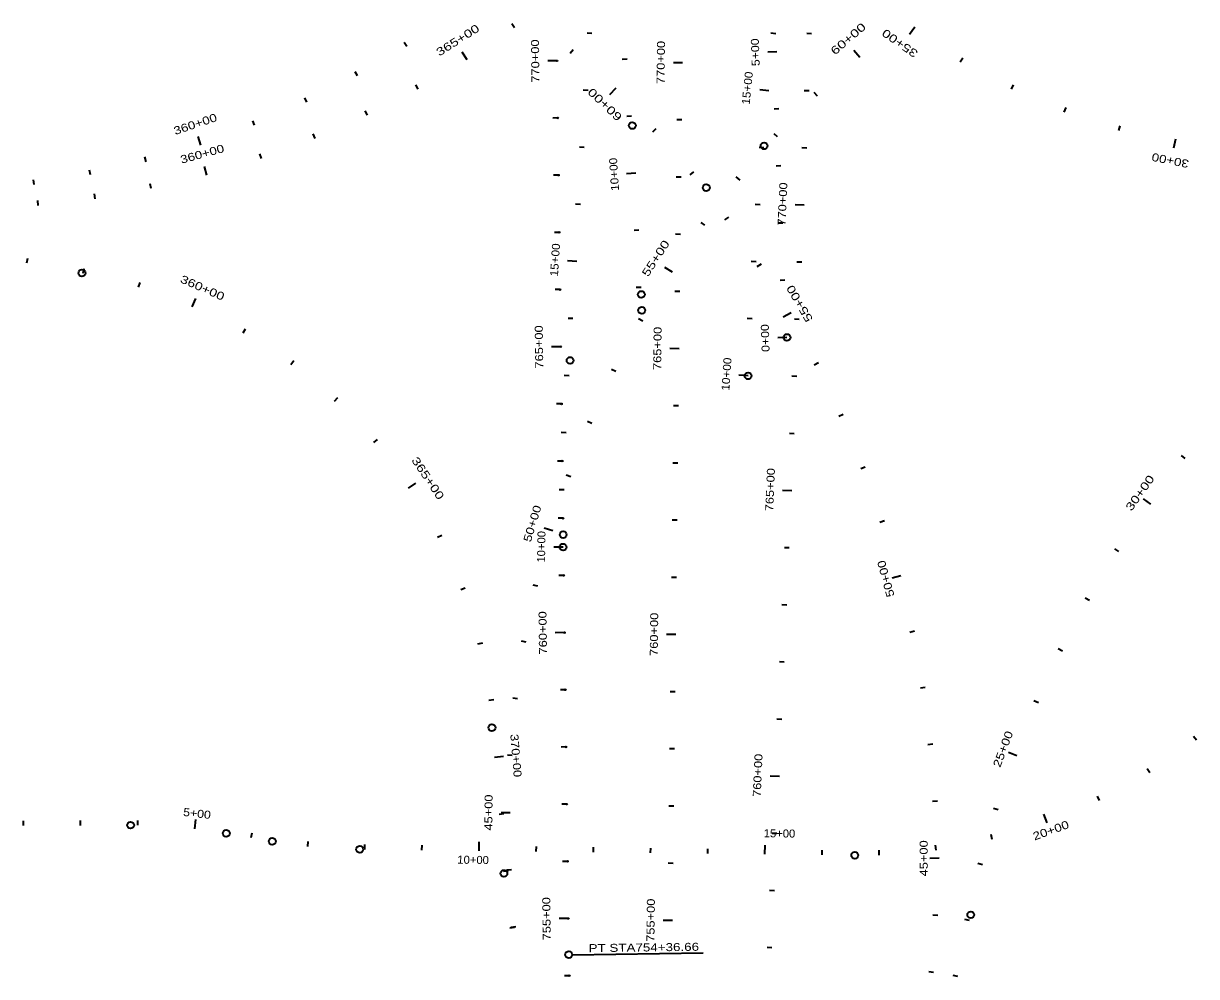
# Model space of a CAD drawing. Extents: x 2357892 to 2370172, y 6966790 to 6985499.
# Drawn here: x 2363338 to 2365390, y 6976228 to 6977895 of the extents above; entities that cross this region are included whole.
import ezdxf
from ezdxf.enums import TextEntityAlignment as Align

# ---------------------------------------------------------------- set-up
doc = ezdxf.new("R2010")
doc.units = 0
doc.header["$LTSCALE"] = 5.6
doc.header["$PDMODE"] = 32
doc.header["$PDSIZE"] = 2.8
doc.layers.add('28', color=7, linetype='Continuous', lineweight=35)
doc.layers.add('7', color=7, linetype='Continuous')

msp = doc.modelspace()

# ---------------------------------------------------------------- linework, layer by layer
at = {"layer": '28'}
for p, q in [((2364196.98, 6977887.49), (2364191.996, 6977894.375)), ((2364332.276, 6977877.606), (2364323.794, 6977878.17)), ((2364653.944, 6977876.548), (2364645.525, 6977877.717)), ((2364716.73, 6977876.916), (2364708.238, 6977877.286)), ((2364896.982, 6977888.495), (2364887.77, 6977875.413)), ((2364008.325, 6977854.335), (2364003.75, 6977861.499)), ((2364114.27, 6977831.311), (2364105.68, 6977844.81)), ((2364299.669, 6977848.715), (2364294.191, 6977842.216)), ((2364393.784, 6977832.501), (2364385.31, 6977831.829)), ((2364656.095, 6977845.54), (2364640.105, 6977844.983)), ((2364800.917, 6977835.329), (2364790.467, 6977847.445)), ((2364981.039, 6977834.378), (2364976.738, 6977827.047)), ((2364271.182, 6977829.601), (2364255.183, 6977829.39)), ((2364490.822, 6977826.107), (2364474.823, 6977826.296)), ((2363922.455, 6977803.116), (2363918.326, 6977810.546)), ((2364028.346, 6977780.183), (2364024.22, 6977787.615)), ((2364325.637, 6977777.826), (2364317.156, 6977778.391)), ((2364374.112, 6977781.967), (2364363.072, 6977770.386)), ((2364641.92, 6977777.279), (2364626.005, 6977778.925)), ((2364712.385, 6977777.011), (2364703.893, 6977777.38)), ((2364727.074, 6977767.895), (2364721.167, 6977774.007)), ((2365069.289, 6977787.407), (2365065.609, 6977779.745)), ((2363833.619, 6977757.236), (2363829.951, 6977764.903)), ((2363939.516, 6977734.289), (2363935.842, 6977741.954)), ((2364272.498, 6977729.609), (2364263.998, 6977729.497)), ((2364401.686, 6977732.813), (2364393.213, 6977732.142)), ((2364659.573, 6977745.6), (2364651.078, 6977745.304)), ((2365161.125, 6977747.905), (2365158.093, 6977739.964)), ((2363742.148, 6977716.864), (2363738.955, 6977724.741)), ((2364444.34, 6977710.8), (2364438.111, 6977705.017)), ((2364489.642, 6977726.114), (2364481.142, 6977726.214)), ((2365255.917, 6977716.144), (2365253.552, 6977707.979)), ((2363648.383, 6977682.151), (2363643.288, 6977697.319)), ((2363848.099, 6977693.793), (2363844.891, 6977701.664)), ((2364657.174, 6977696.383), (2364650.93, 6977702.15)), ((2365353.013, 6977692.341), (2365349.851, 6977676.657)), ((2364318.999, 6977678.047), (2364310.517, 6977678.611)), ((2364633.366, 6977677.65), (2364624.886, 6977678.24)), ((2364708.041, 6977677.105), (2364699.549, 6977677.474)), ((2363552.673, 6977653.228), (2363550.464, 6977661.436)), ((2363754.422, 6977658.841), (2363751.691, 6977666.89)), ((2363455.376, 6977630.201), (2363453.672, 6977638.529)), ((2363658.822, 6977629.557), (2363654.596, 6977644.988)), ((2364273.814, 6977629.618), (2364265.314, 6977629.506)), ((2364408.981, 6977633.081), (2364393.014, 6977632.049)), ((2364510.093, 6977635.477), (2364503.522, 6977630.086)), ((2364591.441, 6977621.023), (2364584.88, 6977626.426)), ((2364663.051, 6977645.661), (2364654.556, 6977645.365)), ((2363356.855, 6977613.158), (2363355.663, 6977621.574)), ((2363561.64, 6977606.046), (2363559.89, 6977614.364)), ((2364488.462, 6977626.121), (2364479.962, 6977626.221)), ((2363463.226, 6977588.394), (2363461.976, 6977596.802)), ((2363363.931, 6977576.663), (2363363.187, 6977585.13)), ((2364312.36, 6977578.268), (2364303.879, 6977578.832)), ((2364626.425, 6977577.891), (2364617.945, 6977578.481)), ((2364703.697, 6977577.2), (2364687.712, 6977577.895)), ((2364530.087, 6977542.057), (2364523.23, 6977547.079)), ((2364571.27, 6977556.39), (2364564.41, 6977551.37)), ((2364666.529, 6977545.721), (2364658.034, 6977545.425)), ((2364275.129, 6977529.627), (2364266.63, 6977529.515)), ((2364414.558, 6977533.238), (2364406.067, 6977532.838)), ((2364487.281, 6977526.128), (2364478.782, 6977526.228)), ((2363344.095, 6977476.375), (2363345.651, 6977484.731)), ((2363442.405, 6977458.069), (2363443.981, 6977466.422)), ((2364305.722, 6977478.488), (2364289.757, 6977479.55)), ((2364473.309, 6977459.739), (2364459.886, 6977468.446)), ((2364619.484, 6977478.133), (2364611.004, 6977478.723)), ((2364628.179, 6977474.176), (2364621.066, 6977469.523)), ((2364699.353, 6977477.294), (2364690.861, 6977477.663)), ((2363539.409, 6977433.996), (2363541.921, 6977442.116)), ((2364670.006, 6977445.782), (2364661.511, 6977445.486)), ((2364276.445, 6977429.635), (2364267.946, 6977429.523)), ((2364418.391, 6977433.313), (2364409.895, 6977433.061)), ((2364486.101, 6977426.135), (2364477.601, 6977426.235)), ((2363633.064, 6977399.096), (2363639.492, 6977413.748)), ((2364680.708, 6977389.097), (2364666.878, 6977381.05)), ((2363722.166, 6977353.819), (2363726.441, 6977361.166)), ((2364299.084, 6977378.709), (2364290.602, 6977379.273)), ((2364421.29, 6977374.334), (2364413.908, 6977378.548)), ((2364612.543, 6977378.374), (2364604.063, 6977378.964)), ((2364695.008, 6977377.388), (2364686.516, 6977377.758)), ((2364673.484, 6977345.842), (2364657.494, 6977345.286)), ((2364277.761, 6977329.644), (2364261.762, 6977329.433)), ((2364484.921, 6977326.142), (2364468.922, 6977326.331)), ((2363805.57, 6977298.745), (2363810.649, 6977305.562)), ((2364728.711, 6977301.385), (2364721.151, 6977297.501)), ((2364292.507, 6977278.925), (2364284.023, 6977279.45)), ((2364374.197, 6977286.117), (2364366.588, 6977289.905)), ((2364605.602, 6977278.615), (2364589.641, 6977279.726)), ((2364690.664, 6977277.483), (2364682.172, 6977277.852)), ((2363882.204, 6977234.585), (2363888.021, 6977240.782)), ((2364279.077, 6977229.653), (2364270.578, 6977229.541)), ((2364483.74, 6977226.149), (2364475.241, 6977226.249)), ((2364332.182, 6977195.371), (2364324.37, 6977198.722)), ((2364772.059, 6977211.281), (2364764.305, 6977207.798)), ((2364287.205, 6977179.067), (2364278.714, 6977179.444)), ((2364686.32, 6977177.577), (2364677.828, 6977177.946)), ((2363951.082, 6977162.161), (2363957.563, 6977167.66)), ((2365370.315, 6977134.135), (2365363.665, 6977139.43)), ((2364280.393, 6977129.661), (2364271.894, 6977129.549)), ((2364482.56, 6977126.156), (2364474.061, 6977126.256)), ((2364810.631, 6977119.032), (2364802.706, 6977115.959)), ((2364295.379, 6977102.39), (2364287.39, 6977105.293)), ((2364011.318, 6977082.406), (2364024.612, 6977091.31)), ((2364283.647, 6977079.132), (2364275.15, 6977079.36)), ((2364681.976, 6977077.672), (2364665.991, 6977078.367)), ((2365310.102, 6977054.31), (2365297.081, 6977063.607)), ((2364263.908, 6977007.471), (2364248.584, 6977012.074)), ((2364281.709, 6977029.67), (2364273.209, 6977029.558)), ((2364481.38, 6977026.163), (2364472.88, 6977026.263)), ((2364844.322, 6977024.891), (2364836.247, 6977022.237)), ((2364062.138, 6976996.345), (2364069.691, 6977000.245)), ((2364281.792, 6976979.15), (2364265.793, 6976979.361)), ((2364677.631, 6976977.766), (2364669.139, 6976978.135)), ((2365254.149, 6976971.442), (2365246.983, 6976976.013)), ((2364283.024, 6976929.678), (2364274.525, 6976929.567)), ((2364873.041, 6976929.115), (2364857.6, 6976924.922)), ((2364102.89, 6976905.084), (2364110.835, 6976908.104)), ((2364237.869, 6976910.921), (2364229.603, 6976912.9)), ((2364480.199, 6976926.17), (2364471.7, 6976926.27)), ((2365202.61, 6976885.76), (2365195.214, 6976889.949)), ((2364673.287, 6976877.86), (2364664.795, 6976878.23)), ((2364284.34, 6976829.687), (2364268.342, 6976829.477)), ((2364479.019, 6976826.177), (2364463.02, 6976826.365)), ((2364896.707, 6976831.967), (2364888.399, 6976830.172)), ((2364133.048, 6976809.796), (2364141.284, 6976811.897)), ((2364217.347, 6976813.049), (2364208.982, 6976814.557)), ((2365155.626, 6976797.498), (2365148.021, 6976801.294)), ((2364668.943, 6976777.955), (2364660.451, 6976778.324)), ((2364285.656, 6976729.696), (2364277.157, 6976729.584)), ((2364477.839, 6976726.184), (2364469.339, 6976726.284)), ((2364915.257, 6976733.715), (2364906.866, 6976732.357)), ((2364152.226, 6976711.707), (2364160.647, 6976712.862)), ((2364202.407, 6976714.171), (2364193.97, 6976715.202)), ((2365113.326, 6976706.898), (2365105.532, 6976710.291)), ((2364664.598, 6976678.049), (2364656.106, 6976678.419)), ((2365390.031, 6976641.604), (2365384.811, 6976648.312)), ((2364286.972, 6976629.704), (2364278.473, 6976629.593)), ((2364476.658, 6976626.191), (2364468.159, 6976626.291)), ((2364928.639, 6976634.626), (2364920.189, 6976633.709)), ((2364161.686, 6976612.171), (2364177.633, 6976613.473)), ((2364193.097, 6976614.606), (2364184.615, 6976615.157)), ((2365075.825, 6976614.208), (2365060.841, 6976619.819)), ((2365308.046, 6976584.426), (2365303.555, 6976591.643)), ((2364660.254, 6976578.144), (2364644.269, 6976578.839)), ((2365220.534, 6976536.132), (2365216.822, 6976543.778)), ((2364288.288, 6976529.713), (2364279.789, 6976529.601)), ((2364475.478, 6976526.198), (2364466.979, 6976526.298)), ((2364936.817, 6976534.972), (2364928.33, 6976534.499)), ((2365043.226, 6976519.683), (2365035.121, 6976522.243)), ((2363337.991, 6976492.349), (2363337.963, 6976500.849)), ((2363437.99, 6976492.683), (2363437.962, 6976501.183)), ((2363537.99, 6976492.934), (2363538.073, 6976501.434)), ((2363637.751, 6976486.721), (2363639.58, 6976502.617)), ((2364169.826, 6976512.503), (2364178.298, 6976513.195)), ((2364189.448, 6976514.672), (2364173.449, 6976514.802)), ((2365128.452, 6976497.249), (2365123.008, 6976512.294)), ((2363736.509, 6976471.126), (2363737.97, 6976479.5)), ((2364655.91, 6976478.238), (2364647.418, 6976478.607)), ((2363835.329, 6976455.968), (2363836.237, 6976464.419)), ((2363935.133, 6976450.457), (2363935.233, 6976458.956)), ((2364035.126, 6976449.276), (2364035.226, 6976457.775)), ((2364135.119, 6976448.095), (2364135.308, 6976464.094)), ((2364635.084, 6976442.192), (2364635.273, 6976458.191)), ((2364934.657, 6976449.316), (2364933.49, 6976457.735)), ((2365032.811, 6976468.204), (2365030.77, 6976476.455)), ((2364235.112, 6976446.915), (2364235.213, 6976455.414)), ((2364335.105, 6976445.734), (2364335.206, 6976454.233)), ((2364435.098, 6976444.553), (2364435.199, 6976453.053)), ((2364535.091, 6976443.373), (2364535.192, 6976451.872)), ((2364735.077, 6976441.011), (2364735.178, 6976449.511)), ((2364835.067, 6976440.79), (2364834.787, 6976449.286)), ((2364289.604, 6976429.722), (2364281.104, 6976429.61)), ((2364474.298, 6976426.204), (2364465.798, 6976426.305)), ((2364939.768, 6976435.027), (2364923.769, 6976434.974)), ((2365015.62, 6976423.581), (2365007.391, 6976425.713)), ((2364177.966, 6976412.835), (2364186.438, 6976413.526)), ((2364191.471, 6976414.693), (2364182.981, 6976414.28)), ((2364651.566, 6976378.332), (2364643.074, 6976378.702)), ((2364937.485, 6976335.065), (2364928.995, 6976335.481)), ((2364188.687, 6976313.424), (2364197.109, 6976314.574)), ((2364199.16, 6976314.989), (2364190.707, 6976314.095)), ((2364290.92, 6976329.73), (2364274.921, 6976329.52)), ((2364473.117, 6976326.211), (2364457.118, 6976326.4)), ((2364993.053, 6976326.171), (2364984.734, 6976327.914)), ((2364647.221, 6976278.427), (2364638.729, 6976278.796)), ((2364297.752, 6976266.475), (2364526.742, 6976269.488)), ((2364929.973, 6976235.359), (2364921.517, 6976236.219)), ((2364292.822, 6976229.753), (2364284.33, 6976229.369)), ((2364972.545, 6976228.297), (2364964.226, 6976230.04))]:
    msp.add_line(p, q, dxfattribs=at)
for centre in [(2364402.985, 6977716.426), (2364633.592, 6977680.897), (2364532.383, 6977607.701), (2363440.27, 6977458.469), (2364418.741, 6977421.052), (2364419.503, 6977393.328), (2364673.484, 6977345.842), (2364294.218, 6977305.58), (2364605.602, 6977278.615), (2364282.079, 6977000.896), (2364281.792, 6976979.15), (2364157.482, 6976663.639), (2363525.41, 6976492.975), (2363692.825, 6976478.752), (2363773.179, 6976464.724), (2363926.132, 6976450.563), (2364792.253, 6976440.336), (2364178.322, 6976408.48), (2364995.15, 6976336.177), (2364291.753, 6976266.396)]:
    msp.add_circle(centre, 6, dxfattribs=at)
at = {"layer": '7'}
for p in [(2364271.182, 6977829.601), (2364272.498, 6977729.609), (2364273.814, 6977629.618), (2364275.129, 6977529.627), (2364276.445, 6977429.635), (2364277.761, 6977329.644), (2364279.077, 6977229.653), (2364280.393, 6977129.661), (2364281.709, 6977029.67), (2364283.024, 6976929.678), (2364284.34, 6976829.687), (2364285.656, 6976729.696), (2364286.972, 6976629.704), (2364288.288, 6976529.713), (2364289.604, 6976429.722), (2364290.92, 6976329.73), (2364292.822, 6976229.753)]:
    msp.add_point(p, dxfattribs=at)

# ---------------------------------------------------------------- texts
at = {"layer": '28'}
for s, rotation, width, p in [('60+00', 40.777, 1.4, (2364785.242, 6977862.747)), ('365+00', 32.47, 1.35, (2364101.387, 6977859.857)), ('35+00', 144.851, 1.35, (2364875.104, 6977865.986)), ('770+00', 90.754, 1.2, (2364240.183, 6977829.284)), ('770+00', 89.324, 1.2, (2364459.826, 6977826.556)), ('5+00', 91.993, 1.15, (2364625.105, 6977844.705)), ('15+00', 84.094, 1.1, (2364611.159, 6977781.189)), ('60+00', 136.369, 1.4, (2364359.911, 6977758.185)), ('360+00', 18.565, 1.25, (2363640.741, 6977712.287)), ('360+00', 15.315, 1.25, (2363652.483, 6977659.962)), ('30+00', 168.601, 1.25, (2365345.502, 6977662.231)), ('10+00', 93.697, 1.1, (2364378.016, 6977631.534)), ('770+00', 87.51, 1.2, (2364672.74, 6977578.85)), ('15+00', 86.194, 1.1, (2364274.821, 6977481.01)), ('55+00', 57.03, 1.35, (2364449.773, 6977480.419)), ('360+00', 336.313, 1.3, (2363648.331, 6977426.25)), ('55+00', 120.191, 1.35, (2364701.719, 6977408.53)), ('765+00', 90.754, 1.2, (2364246.762, 6977329.328)), ('765+00', 89.324, 1.2, (2364453.924, 6977326.59)), ('0+00', 91.993, 1.15, (2364642.494, 6977345.008)), ('10+00', 86.02, 1.1, (2364574.71, 6977281.254)), ('365+00', 303.813, 1.35, (2364039.684, 6977095.761)), ('765+00', 87.51, 1.2, (2364651.018, 6977079.322)), ('30+00', 54.472, 1.35, (2365296.73, 6977069.999)), ('50+00', 73.282, 1.25, (2364234.824, 6977018.403)), ('10+00', 89.243, 1.05, (2364250.796, 6976979.653)), ('50+00', 105.191, 1.25, (2364853.242, 6976925.709)), ('760+00', 90.754, 1.2, (2364253.342, 6976829.371)), ('760+00', 89.324, 1.2, (2364448.022, 6976826.624)), ('370+00', 274.669, 1.2, (2364192.63, 6976614.124)), ('25+00', 69.472, 1.25, (2365058.014, 6976623.676)), ('760+00', 87.51, 1.2, (2364629.297, 6976579.793)), ('45+00', 89.534, 1.2, (2364158.45, 6976514.982)), ('5+00', 353.436, 1.15, (2363640.836, 6976506.499)), ('20+00', 19.893, 1.25, (2365137.563, 6976477.329)), ('15+00', 359.323, 1.05, (2364660.386, 6976471.565)), ('45+00', 90.191, 1.2, (2364919.768, 6976434.984)), ('10+00', 359.323, 1.05, (2364124.472, 6976425.35)), ('755+00', 90.754, 1.2, (2364259.921, 6976329.415)), ('755+00', 89.324, 1.2, (2364442.121, 6976326.66))]:
    msp.add_text(s, height=14, rotation=rotation, dxfattribs=dict(at, width=width)).set_placement(p, align=Align.CENTER)
at = {"layer": '28', "width": 1.25}
msp.add_text('PT STA754+36.66', height=14, rotation=0.754, dxfattribs=at).set_placement((2364326.697, 6976270.856))

doc.saveas('drawing.dxf')
